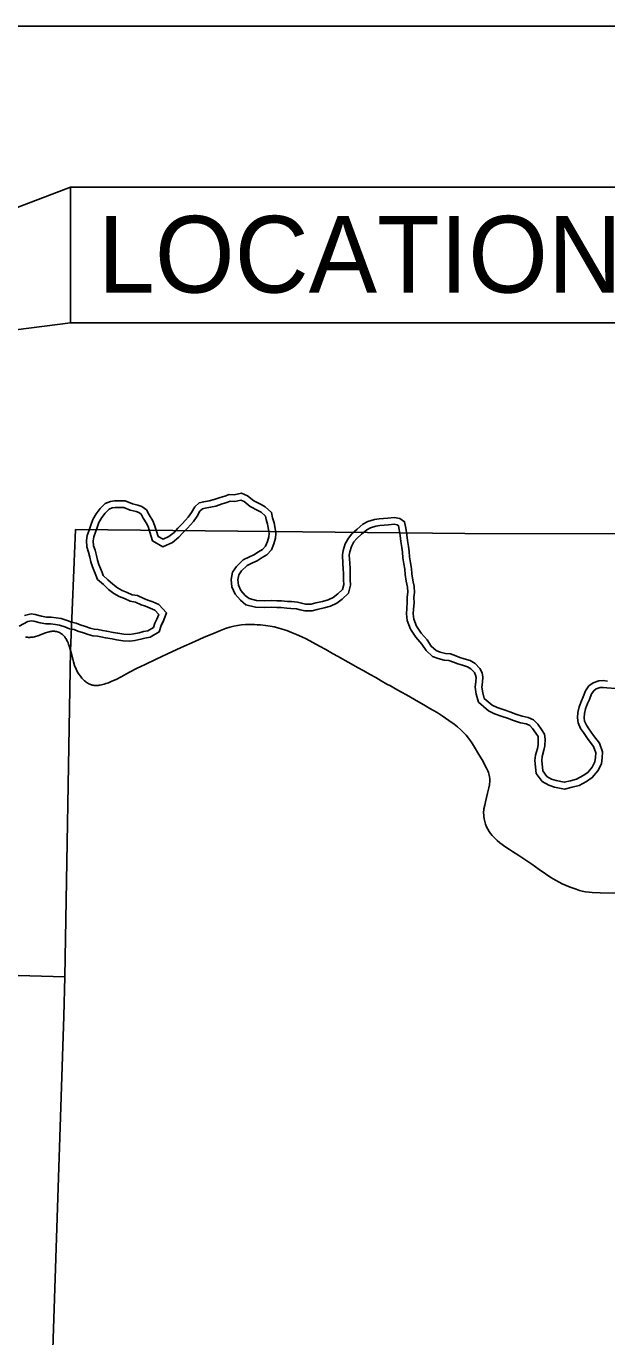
# Model space of a CAD drawing. Extents: x -12.1 to 34, y 0 to 22.
# Drawn here: x -8.877 to -7.59, y 17.402 to 20.306 of the extents above; entities that cross this region are included whole.
import ezdxf

# ---------------------------------------------------------------- set-up
doc = ezdxf.new("R2010")
doc.units = 0
for name, color, linetype in [('BR_P_Gen_Text', 7, 'Continuous'), ('GM_X_Major_River', 7, 'Continuous'), ('GM_X_State_Route', 7, 'Continuous'), ('GM_X_Township', 7, 'Continuous'), ('SH_Text', 7, 'Continuous')]:
    doc.layers.add(name, color=color, linetype=linetype)

msp = doc.modelspace()

# ---------------------------------------------------------------- linework, layer by layer
at = {"layer": 'BR_P_Gen_Text'}
for points in [[(-8.7792, 19.9493), (-8.7792, 19.649), (-9.9694, 19.4964)], [(-8.7792, 19.9493), (-7.2191, 19.9493), (-7.2191, 19.649), (-8.7792, 19.649)]]:
    msp.add_lwpolyline(points, close=True, dxfattribs=at)
at = {"layer": 'GM_X_Major_River'}
for points in [[(-8.1737, 19.0792), (-8.1733, 19.0693), (-8.1764, 19.0579), (-8.1863, 19.0482), (-8.1965, 19.0406), (-8.2082, 19.0349), (-8.2206, 19.0316), (-8.2355, 19.0283), (-8.2454, 19.0257), (-8.2578, 19.0256), (-8.2667, 19.0277), (-8.2759, 19.0297), (-8.2891, 19.0311), (-8.2983, 19.0317), (-8.3111, 19.0327), (-8.3214, 19.0329), (-8.3339, 19.0336), (-8.3484, 19.0327), (-8.3665, 19.0333), (-8.3832, 19.0378), (-8.3922, 19.0448), (-8.4015, 19.0554), (-8.4069, 19.0675), (-8.4081, 19.0792), (-8.406, 19.0906), (-8.3997, 19.0995), (-8.3877, 19.1114), (-8.3757, 19.1171), (-8.3655, 19.1218), (-8.3545, 19.1287), (-8.3439, 19.1348), (-8.3337, 19.1459), (-8.3281, 19.1595), (-8.325, 19.1716), (-8.3237, 19.1819), (-8.3252, 19.1933), (-8.3278, 19.206), (-8.3311, 19.217), (-8.3337, 19.2288), (-8.3476, 19.2411), (-8.3565, 19.2464), (-8.3726, 19.2548), (-8.3865, 19.2657), (-8.4, 19.2713), (-8.416, 19.2679), (-8.4274, 19.2686), (-8.4373, 19.2649), (-8.4472, 19.2617), (-8.461, 19.2573), (-8.4716, 19.2547), (-8.4837, 19.2525), (-8.4936, 19.2503), (-8.5038, 19.241), (-8.5112, 19.2285), (-8.5182, 19.2181), (-8.5305, 19.2041), (-8.5411, 19.1937), (-8.5492, 19.1844), (-8.5612, 19.1751), (-8.5739, 19.1693), (-8.5849, 19.1756), (-8.5893, 19.1891), (-8.5926, 19.2005), (-8.5969, 19.21), (-8.6049, 19.2235), (-8.611, 19.2344), (-8.621, 19.2422), (-8.6299, 19.245), (-8.642, 19.2477), (-8.658, 19.2547), (-8.6701, 19.2543), (-8.6814, 19.2545), (-8.6907, 19.253), (-8.702, 19.2483), (-8.7136, 19.2372), (-8.7224, 19.2254), (-8.7297, 19.2129), (-8.7343, 19.2004), (-8.7381, 19.1897), (-8.7419, 19.178), (-8.7436, 19.1662), (-8.7428, 19.1524), (-8.7391, 19.1407), (-8.7362, 19.1297), (-8.734, 19.119), (-8.7303, 19.1084), (-8.7227, 19.09), (-8.7191, 19.0804), (-8.7062, 19.0687), (-8.6948, 19.0582), (-8.683, 19.0494), (-8.6712, 19.0423), (-8.6591, 19.0378), (-8.6466, 19.0322), (-8.6353, 19.0302), (-8.6224, 19.0242), (-8.6132, 19.0207), (-8.6025, 19.0169), (-8.5925, 19.0124), (-8.5835, 19.0028), (-8.5877, 18.9925)], [(-8.1589, 19.0799), (-8.1583, 19.0676), (-8.1631, 19.0501), (-8.1766, 19.0368), (-8.1887, 19.0279), (-8.2029, 19.0209), (-8.217, 19.0171), (-8.232, 19.0138), (-8.2434, 19.0108), (-8.2595, 19.0107), (-8.27, 19.0132), (-8.2783, 19.015), (-8.2904, 19.0162), (-8.2994, 19.0169), (-8.3119, 19.0178), (-8.322, 19.0181), (-8.3338, 19.0187), (-8.3482, 19.0178), (-8.3687, 19.0185), (-8.3901, 19.0242), (-8.4025, 19.034), (-8.4141, 19.0473), (-8.4215, 19.0636), (-8.4231, 19.0798), (-8.4201, 19.0965), (-8.4111, 19.1092), (-8.3964, 19.1237), (-8.382, 19.1306), (-8.3725, 19.135), (-8.3622, 19.1414), (-8.3533, 19.1466), (-8.3465, 19.154), (-8.3423, 19.1642), (-8.3397, 19.1744), (-8.3387, 19.1819), (-8.3399, 19.1908), (-8.3422, 19.2024), (-8.3455, 19.2133), (-8.3472, 19.2208), (-8.3564, 19.229), (-8.3638, 19.2334), (-8.3807, 19.2422), (-8.3941, 19.2527), (-8.4015, 19.2558), (-8.4149, 19.253), (-8.4251, 19.2535), (-8.4324, 19.2509), (-8.4426, 19.2475), (-8.457, 19.243), (-8.4685, 19.2402), (-8.4807, 19.2379), (-8.4865, 19.2366), (-8.4921, 19.2315), (-8.4986, 19.2205), (-8.5064, 19.209), (-8.5197, 19.1939), (-8.5302, 19.1836), (-8.5389, 19.1736), (-8.5534, 19.1623), (-8.5747, 19.1526), (-8.5973, 19.1656), (-8.6035, 19.1847), (-8.6066, 19.1953), (-8.6102, 19.2032), (-8.6178, 19.2161), (-8.6225, 19.2246), (-8.628, 19.2288), (-8.6338, 19.2306), (-8.6467, 19.2335), (-8.6609, 19.2397), (-8.67, 19.2394), (-8.6804, 19.2396), (-8.6866, 19.2386), (-8.6937, 19.2357), (-8.7024, 19.2273), (-8.71, 19.2172), (-8.7162, 19.2066), (-8.7203, 19.1954), (-8.724, 19.185), (-8.7273, 19.1746), (-8.7286, 19.1656), (-8.728, 19.1551), (-8.7248, 19.1448), (-8.7217, 19.1331), (-8.7196, 19.123), (-8.7164, 19.1136), (-8.7089, 19.0954), (-8.7064, 19.089), (-8.6962, 19.0797), (-8.6852, 19.0696), (-8.6747, 19.0617), (-8.6647, 19.0558), (-8.6534, 19.0516), (-8.6422, 19.0465), (-8.6307, 19.0445), (-8.6167, 19.038), (-8.608, 19.0347), (-8.5969, 19.0307), (-8.5837, 19.0247), (-8.5662, 19.0061), (-8.5739, 18.9869)], [(-8.5741, 18.9865), (-8.5662, 19.0061), (-8.5837, 19.0247), (-8.5969, 19.0307), (-8.608, 19.0347), (-8.6167, 19.038), (-8.6307, 19.0445), (-8.6422, 19.0465), (-8.6534, 19.0516), (-8.6647, 19.0558), (-8.6747, 19.0617), (-8.6852, 19.0696), (-8.6962, 19.0797), (-8.7064, 19.089), (-8.7089, 19.0954), (-8.7164, 19.1136), (-8.7196, 19.123), (-8.7217, 19.1331), (-8.7248, 19.1448), (-8.728, 19.1551), (-8.7286, 19.1656), (-8.7273, 19.1746), (-8.724, 19.185), (-8.7203, 19.1954), (-8.7162, 19.2066), (-8.71, 19.2172), (-8.7024, 19.2273), (-8.6937, 19.2357), (-8.6866, 19.2386), (-8.6804, 19.2396), (-8.67, 19.2394), (-8.6609, 19.2397), (-8.6467, 19.2335), (-8.6338, 19.2306), (-8.628, 19.2288), (-8.6225, 19.2246), (-8.6178, 19.2161), (-8.6102, 19.2032), (-8.6066, 19.1953), (-8.6035, 19.1847), (-8.5973, 19.1656), (-8.5747, 19.1526), (-8.5534, 19.1623), (-8.5389, 19.1736), (-8.5302, 19.1836), (-8.5197, 19.1939), (-8.5064, 19.209), (-8.4986, 19.2205), (-8.4921, 19.2315), (-8.4865, 19.2366), (-8.4807, 19.2379), (-8.4685, 19.2402), (-8.457, 19.243), (-8.4426, 19.2475), (-8.4324, 19.2509), (-8.4251, 19.2535), (-8.4149, 19.253), (-8.4015, 19.2558), (-8.3941, 19.2527), (-8.3807, 19.2422), (-8.3638, 19.2334), (-8.3564, 19.229), (-8.3472, 19.2208), (-8.3455, 19.2133), (-8.3422, 19.2024), (-8.3399, 19.1908), (-8.3387, 19.1819), (-8.3397, 19.1744), (-8.3423, 19.1642), (-8.3465, 19.154), (-8.3533, 19.1466), (-8.3622, 19.1414), (-8.3725, 19.135), (-8.382, 19.1306), (-8.3964, 19.1237), (-8.4111, 19.1092), (-8.4201, 19.0965), (-8.4231, 19.0798), (-8.4215, 19.0636), (-8.4141, 19.0473), (-8.4025, 19.034), (-8.3901, 19.0242), (-8.3687, 19.0185), (-8.3482, 19.0178), (-8.3338, 19.0187), (-8.322, 19.0181), (-8.3119, 19.0178), (-8.2994, 19.0169), (-8.2904, 19.0162), (-8.2783, 19.015), (-8.27, 19.0132), (-8.2595, 19.0107), (-8.2434, 19.0108), (-8.232, 19.0138), (-8.217, 19.0171), (-8.2029, 19.0209), (-8.1887, 19.0279), (-8.1766, 19.0368), (-8.1631, 19.0501), (-8.1583, 19.0676), (-8.1589, 19.0799)], [(-7.5886, 18.855), (-7.5982, 18.856), (-7.6081, 18.8553), (-7.6202, 18.8509), (-7.6297, 18.8444), (-7.6374, 18.8333), (-7.6423, 18.8201), (-7.6465, 18.8109), (-7.6513, 18.7977), (-7.6541, 18.7856), (-7.6551, 18.7735), (-7.6539, 18.7624), (-7.6481, 18.75), (-7.642, 18.7408), (-7.6316, 18.7253), (-7.6194, 18.7104), (-7.6147, 18.6962), (-7.6153, 18.6859), (-7.6163, 18.676), (-7.6226, 18.6642), (-7.6324, 18.6524), (-7.6427, 18.6455), (-7.6571, 18.6376), (-7.6706, 18.6343), (-7.6844, 18.631), (-7.7026, 18.6348), (-7.7129, 18.6379), (-7.7232, 18.6438), (-7.7322, 18.6559), (-7.7345, 18.679), (-7.7335, 18.6879), (-7.7297, 18.7021), (-7.7273, 18.7114), (-7.7271, 18.7263), (-7.7279, 18.7377), (-7.7351, 18.748), (-7.743, 18.7596), (-7.7523, 18.7688), (-7.7641, 18.7744), (-7.7779, 18.7771), (-7.7915, 18.7817), (-7.805, 18.7872), (-7.8178, 18.7911), (-7.8335, 18.7963), (-7.8442, 18.8015), (-7.8617, 18.8167), (-7.865, 18.8291), (-7.8669, 18.8419), (-7.8655, 18.8529), (-7.8649, 18.8636), (-7.8667, 18.8732), (-7.8714, 18.8831), (-7.8822, 18.8937), (-7.8929, 18.9004), (-7.9061, 18.9045), (-7.9157, 18.9073), (-7.9249, 18.9108), (-7.9367, 18.9153), (-7.948, 18.9163), (-7.9594, 18.9191), (-7.9687, 18.9226), (-7.9794, 18.9324), (-7.9884, 18.9462), (-8.0017, 18.9614), (-8.0121, 18.977), (-8.0182, 18.9926), (-8.0194, 19.0043), (-8.0188, 19.0146), (-8.0175, 19.0281), (-8.0176, 19.0406), (-8.0166, 19.0516), (-8.0171, 19.0648), (-8.02, 19.079), (-8.0223, 19.0928), (-8.0234, 19.1046), (-8.0253, 19.117), (-8.0272, 19.1301), (-8.0283, 19.1422), (-8.0298, 19.1536), (-8.0321, 19.1667), (-8.0336, 19.1791), (-8.0355, 19.1937), (-8.0385, 19.2083), (-8.0492, 19.2156), (-8.0613, 19.2173), (-8.0758, 19.2161), (-8.085, 19.215), (-8.095, 19.2146), (-8.1052, 19.2131), (-8.1198, 19.2087), (-8.1307, 19.2026), (-8.1438, 19.1918), (-8.1554, 19.1814), (-8.1631, 19.1717), (-8.1701, 19.1593), (-8.1746, 19.1446), (-8.176, 19.1347), (-8.1751, 19.1151), (-8.1743, 19.1041), (-8.1742, 19.0934), (-8.1737, 19.0792)], [(-7.5901, 18.8402), (-7.5984, 18.8411), (-7.605, 18.8406), (-7.6134, 18.8375), (-7.6191, 18.8337), (-7.6241, 18.8264), (-7.6285, 18.8145), (-7.6327, 18.8052), (-7.637, 18.7934), (-7.6393, 18.7833), (-7.6401, 18.7736), (-7.6394, 18.7665), (-7.6351, 18.7573), (-7.6296, 18.7491), (-7.6196, 18.7342), (-7.6061, 18.7177), (-7.5996, 18.6982), (-7.6005, 18.6847), (-7.6018, 18.6716), (-7.6102, 18.6558), (-7.6224, 18.6412), (-7.6349, 18.6328), (-7.6517, 18.6236), (-7.6671, 18.6198), (-7.6842, 18.6157), (-7.7062, 18.6203), (-7.7188, 18.6241), (-7.7333, 18.6325), (-7.7466, 18.6503), (-7.7495, 18.6791), (-7.7482, 18.6906), (-7.7441, 18.7059), (-7.7422, 18.7134), (-7.742, 18.7259), (-7.7425, 18.7325), (-7.7473, 18.7395), (-7.7545, 18.7501), (-7.761, 18.7565), (-7.7688, 18.7602), (-7.7817, 18.7627), (-7.7967, 18.7677), (-7.81, 18.7732), (-7.8223, 18.7769), (-7.8391, 18.7825), (-7.8524, 18.789), (-7.8749, 18.8084), (-7.8796, 18.8261), (-7.8819, 18.8417), (-7.8803, 18.8543), (-7.8799, 18.8626), (-7.881, 18.8685), (-7.8838, 18.8744), (-7.8915, 18.882), (-7.8992, 18.8868), (-7.9104, 18.8903), (-7.9204, 18.8932), (-7.9302, 18.8969), (-7.9401, 18.9007), (-7.9504, 18.9016), (-7.9638, 18.9048), (-7.9766, 18.9097), (-7.9909, 18.9227), (-8.0003, 18.9372), (-8.0135, 18.9524), (-8.0253, 18.97), (-8.0329, 18.9891), (-8.0343, 19.004), (-8.0336, 19.0158), (-8.0324, 19.0288), (-8.0325, 19.0412), (-8.0315, 19.052), (-8.0319, 19.063), (-8.0347, 19.0763), (-8.037, 19.0909), (-8.0382, 19.1027), (-8.04, 19.1148), (-8.042, 19.1284), (-8.0431, 19.1405), (-8.0446, 19.1513), (-8.0468, 19.1646), (-8.0484, 19.1773), (-8.0502, 19.1913), (-8.0519, 19.1994), (-8.0547, 19.2014), (-8.0617, 19.2024), (-8.0743, 19.2013), (-8.0838, 19.2002), (-8.0936, 19.1998), (-8.102, 19.1985), (-8.1139, 19.1949), (-8.1223, 19.1902), (-8.1341, 19.1805), (-8.1446, 19.1711), (-8.1507, 19.1634), (-8.1564, 19.1534), (-8.16, 19.1414), (-8.161, 19.134), (-8.1602, 19.116), (-8.1594, 19.1047), (-8.1593, 19.0937), (-8.1589, 19.0797)], [(-8.1589, 19.0799), (-8.1593, 19.0937), (-8.1594, 19.1047), (-8.1602, 19.116), (-8.161, 19.134), (-8.16, 19.1414), (-8.1564, 19.1534), (-8.1507, 19.1634), (-8.1446, 19.1711), (-8.1341, 19.1805), (-8.1223, 19.1902), (-8.1139, 19.1949), (-8.102, 19.1985), (-8.0936, 19.1998), (-8.0838, 19.2002), (-8.0743, 19.2013), (-8.0617, 19.2024), (-8.0547, 19.2014), (-8.0519, 19.1994), (-8.0502, 19.1913), (-8.0484, 19.1773), (-8.0468, 19.1646), (-8.0446, 19.1513), (-8.0431, 19.1405), (-8.042, 19.1284), (-8.04, 19.1148), (-8.0382, 19.1027), (-8.037, 19.0909), (-8.0347, 19.0763), (-8.0319, 19.063), (-8.0315, 19.052), (-8.0325, 19.0412), (-8.0324, 19.0288), (-8.0336, 19.0158), (-8.0343, 19.004), (-8.0329, 18.9891), (-8.0253, 18.97), (-8.0135, 18.9524), (-8.0003, 18.9372), (-7.9909, 18.9227), (-7.9766, 18.9097), (-7.9638, 18.9048), (-7.9504, 18.9016), (-7.9401, 18.9007), (-7.9302, 18.8969), (-7.9204, 18.8932), (-7.9104, 18.8903), (-7.8992, 18.8868), (-7.8915, 18.882), (-7.8838, 18.8744), (-7.881, 18.8685), (-7.8799, 18.8626), (-7.8803, 18.8543), (-7.8819, 18.8417), (-7.8796, 18.8261), (-7.8749, 18.8084), (-7.8524, 18.789), (-7.8391, 18.7825), (-7.8223, 18.7769), (-7.81, 18.7732), (-7.7967, 18.7677), (-7.7817, 18.7627), (-7.7688, 18.7602), (-7.761, 18.7565), (-7.7545, 18.7501), (-7.7473, 18.7395), (-7.7425, 18.7325), (-7.742, 18.7259), (-7.7422, 18.7134), (-7.7441, 18.7059), (-7.7482, 18.6906), (-7.7495, 18.6791), (-7.7466, 18.6503), (-7.7333, 18.6325), (-7.7188, 18.6241), (-7.7062, 18.6203), (-7.6842, 18.6157), (-7.6671, 18.6198), (-7.6517, 18.6236), (-7.6349, 18.6328), (-7.6224, 18.6412), (-7.6102, 18.6558), (-7.6018, 18.6716), (-7.6005, 18.6847), (-7.5996, 18.6982), (-7.6061, 18.7177), (-7.6196, 18.7342), (-7.6296, 18.7491), (-7.6351, 18.7573), (-7.6394, 18.7665), (-7.6401, 18.7736), (-7.6393, 18.7833), (-7.637, 18.7934), (-7.6327, 18.8052), (-7.6285, 18.8145), (-7.6241, 18.8264), (-7.6191, 18.8337), (-7.6134, 18.8375), (-7.605, 18.8406), (-7.5984, 18.8411), (-7.5902, 18.8403)], [(-8.5877, 18.9925), (-8.5919, 18.9836), (-8.595, 18.9739), (-8.6074, 18.9667), (-8.6177, 18.9649), (-8.6269, 18.962), (-8.6389, 18.9594), (-8.6482, 18.9582), (-8.6606, 18.9592), (-8.6745, 18.9609), (-8.6844, 18.9629), (-8.699, 18.9653), (-8.7086, 18.9674), (-8.7175, 18.9691), (-8.7267, 18.9701), (-8.7356, 18.9725), (-8.7459, 18.9763), (-8.7577, 18.9794), (-8.7666, 18.9833), (-8.7769, 18.9853), (-8.7865, 18.9892), (-8.8, 18.9937), (-8.8107, 18.9954), (-8.8224, 18.9967), (-8.8324, 18.997), (-8.8434, 18.9987), (-8.8576, 19.0025), (-8.8665, 19.0039), (-8.8811, 19.0007)], [(-8.8737, 18.9874), (-8.8932, 18.9765)], [(-8.5743, 18.9862), (-8.578, 18.9781), (-8.5826, 18.964), (-8.6022, 18.9526), (-8.6141, 18.9504), (-8.6231, 18.9476), (-8.6365, 18.9447), (-8.6478, 18.9433), (-8.6621, 18.9444), (-8.6769, 18.9462), (-8.6871, 18.9483), (-8.7017, 18.9507), (-8.7116, 18.9528), (-8.7197, 18.9544), (-8.7295, 18.9554), (-8.7402, 18.9583), (-8.7504, 18.9621), (-8.7626, 18.9653), (-8.771, 18.969), (-8.7812, 18.971), (-8.7916, 18.9752), (-8.8036, 18.9792), (-8.8127, 18.9807), (-8.8235, 18.9819), (-8.8337, 18.9822), (-8.8465, 18.9841), (-8.8607, 18.9879), (-8.8663, 18.9888), (-8.8737, 18.9874)], [(-8.8737, 18.9874), (-8.8663, 18.9888), (-8.8607, 18.9879), (-8.8465, 18.9841), (-8.8337, 18.9822), (-8.8235, 18.9819), (-8.8127, 18.9807), (-8.8036, 18.9792), (-8.7916, 18.9752), (-8.7812, 18.971), (-8.771, 18.969), (-8.7626, 18.9653), (-8.7504, 18.9621), (-8.7402, 18.9583), (-8.7295, 18.9554), (-8.7197, 18.9544), (-8.7116, 18.9528), (-8.7017, 18.9507), (-8.6871, 18.9483), (-8.6769, 18.9462), (-8.6621, 18.9444), (-8.6478, 18.9433), (-8.6365, 18.9447), (-8.6231, 18.9476), (-8.6141, 18.9504), (-8.6022, 18.9526), (-8.5826, 18.964), (-8.578, 18.9781), (-8.5741, 18.9865)], [(-7.5902, 18.8403), (-7.5699, 18.8383)]]:
    msp.add_lwpolyline(points, dxfattribs=at)
at = {"layer": 'GM_X_State_Route'}
for points in [[(-8.8793, 18.953), (-8.877, 18.9525), (-8.8748, 18.9522), (-8.8723, 18.9519), (-8.8697, 18.9519), (-8.8669, 18.952), (-8.8643, 18.9522), (-8.8617, 18.9526), (-8.8593, 18.9531), (-8.8567, 18.9538), (-8.8513, 18.9556), (-8.8349, 18.9619), (-8.8294, 18.9637), (-8.8268, 18.9644), (-8.8242, 18.9649), (-8.8221, 18.9652), (-8.82, 18.9654), (-8.8184, 18.9654), (-8.8164, 18.9654), (-8.8144, 18.9653), (-8.8123, 18.9651), (-8.8103, 18.9647), (-8.8082, 18.9642), (-8.8059, 18.9634), (-8.8039, 18.9626), (-8.8021, 18.9617), (-8.8006, 18.9607), (-8.799, 18.9597), (-8.7967, 18.9579), (-8.7949, 18.9563), (-8.7933, 18.9545), (-8.792, 18.9528), (-8.7908, 18.9512), (-8.7895, 18.9492), (-8.7882, 18.9472), (-8.787, 18.9449), (-8.7858, 18.9425), (-8.7846, 18.9395), (-8.7834, 18.9365), (-8.7815, 18.9309), (-8.7791, 18.9231), (-8.7787, 18.9217)], [(-8.7787, 18.9217), (-8.7758, 18.9106), (-8.7726, 18.8976), (-8.7701, 18.8893), (-8.767, 18.8813), (-8.7635, 18.8747), (-8.761, 18.8707), (-8.7573, 18.8656), (-8.754, 18.8616), (-8.7516, 18.859), (-8.7496, 18.8571), (-8.7479, 18.8556), (-8.7461, 18.8541), (-8.7444, 18.8528), (-8.7424, 18.8514), (-8.7405, 18.8501), (-8.7382, 18.8489), (-8.7364, 18.8481), (-8.7347, 18.8474), (-8.7327, 18.8467), (-8.7311, 18.8463), (-8.729, 18.8458), (-8.7266, 18.8455), (-8.7242, 18.8454), (-8.7221, 18.8453), (-8.7201, 18.8454), (-8.7181, 18.8456), (-8.7158, 18.8459), (-8.7135, 18.8462), (-8.7105, 18.8468), (-8.7073, 18.8475), (-8.7044, 18.8483), (-8.7012, 18.8493), (-8.6982, 18.8503), (-8.6952, 18.8514), (-8.6872, 18.8547), (-8.6783, 18.8589), (-8.6669, 18.8647), (-8.6484, 18.8745), (-8.6329, 18.8826), (-8.6221, 18.8882), (-8.6154, 18.8912), (-8.6136, 18.8921), (-8.5894, 18.9034), (-8.5641, 18.9152), (-8.5335, 18.9296), (-8.5037, 18.943), (-8.4829, 18.9522), (-8.4625, 18.9608), (-8.4468, 18.9671), (-8.4353, 18.9713), (-8.4258, 18.9742), (-8.4173, 18.9764), (-8.4087, 18.9781), (-8.4, 18.9794), (-8.3913, 18.9802), (-8.382, 18.9804), (-8.3715, 18.9802), (-8.3651, 18.9799), (-8.3576, 18.9794), (-8.3471, 18.9783), (-8.3367, 18.9768), (-8.3275, 18.975), (-8.3195, 18.9731), (-8.31, 18.9703), (-8.2995, 18.9668), (-8.2891, 18.9629), (-8.2783, 18.9584), (-8.2661, 18.9529), (-8.2566, 18.9483), (-8.2417, 18.9404), (-8.2269, 18.9322), (-8.2132, 18.9247), (-8.1984, 18.9164), (-8.1857, 18.9093), (-8.1704, 18.9008), (-8.1572, 18.8934), (-8.143, 18.8854), (-8.1287, 18.8775), (-8.1165, 18.8707), (-8.1024, 18.8626), (-8.0902, 18.8557), (-8.0776, 18.8485), (-8.07, 18.8442), (-8.0588, 18.8379), (-8.0451, 18.8302), (-8.0344, 18.8244), (-8.0165, 18.8145), (-7.992, 18.8001), (-7.9825, 18.7945), (-7.9664, 18.7851), (-7.9555, 18.7783), (-7.9478, 18.7732), (-7.9401, 18.7679), (-7.9284, 18.7595), (-7.921, 18.7538), (-7.9145, 18.748), (-7.9079, 18.7414), (-7.902, 18.7349), (-7.8968, 18.7286), (-7.8923, 18.7225), (-7.888, 18.7163), (-7.8831, 18.7083), (-7.8736, 18.6923), (-7.8645, 18.6767), (-7.8602, 18.669), (-7.8567, 18.6623), (-7.8538, 18.6558), (-7.8526, 18.6525), (-7.8517, 18.6495), (-7.8508, 18.6463), (-7.8502, 18.6425), (-7.8497, 18.6387), (-7.8497, 18.6349), (-7.8498, 18.631), (-7.8501, 18.6282), (-7.8505, 18.6252), (-7.8517, 18.6182), (-7.8545, 18.6063), (-7.8592, 18.5876), (-7.8609, 18.5803), (-7.8626, 18.5718), (-7.863, 18.5687), (-7.8632, 18.5651), (-7.8632, 18.5621), (-7.8631, 18.5589), (-7.8628, 18.5552), (-7.8618, 18.5496), (-7.8606, 18.544), (-7.8587, 18.5379), (-7.8565, 18.532), (-7.854, 18.5268), (-7.8511, 18.5219), (-7.8478, 18.5171), (-7.8442, 18.5127), (-7.8394, 18.5077), (-7.8331, 18.5017), (-7.8273, 18.4969), (-7.8218, 18.4926), (-7.8161, 18.4887), (-7.8057, 18.4816), (-7.7989, 18.4771), (-7.7853, 18.4682), (-7.7722, 18.4596), (-7.7566, 18.4492), (-7.7401, 18.4377), (-7.7263, 18.428), (-7.7141, 18.42), (-7.7042, 18.4141), (-7.6956, 18.4092), (-7.6889, 18.4058), (-7.6805, 18.402), (-7.6713, 18.3983), (-7.6582, 18.3936), (-7.6505, 18.3911), (-7.6449, 18.3897), (-7.6375, 18.3883), (-7.6289, 18.3872), (-7.6226, 18.3867), (-7.6046, 18.3861), (-7.5556, 18.3853)]]:
    msp.add_lwpolyline(points, dxfattribs=at)
at = {"layer": 'GM_X_Township'}
for points in [[(-8.8204, 17.3082), (-8.7941, 18.1122), (-8.7921, 18.1999), (-8.7789, 18.9222), (-8.7681, 19.1909), (-7.9046, 19.1821), (-6.8924, 19.1805)], [(-9.2578, 18.2131), (-8.7921, 18.1999)]]:
    msp.add_lwpolyline(points, dxfattribs=at)
at = {"layer": 'SH_Text'}
msp.add_lwpolyline([(-12.1463, 20.3063), (-4.4383, 20.3063), (-4.4383, 10.9773), (-12.1463, 10.9773)], close=True, dxfattribs=at)

# ---------------------------------------------------------------- texts
at = {"layer": 'BR_P_Gen_Text'}
msp.add_text('LOCATION 21', height=0.17, dxfattribs=at).set_placement((-8.7185, 19.7159))

doc.saveas('drawing.dxf')
